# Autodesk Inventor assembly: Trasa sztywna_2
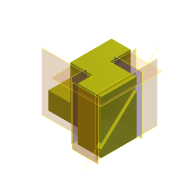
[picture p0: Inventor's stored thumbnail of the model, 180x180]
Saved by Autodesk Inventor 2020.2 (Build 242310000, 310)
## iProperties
Created: 2014-07
Part Number: Trasa sztywna_2
Document SubType Name: Assembly
Designer: F.Stasiak
Catalog Web Link: www.expertbooks.pl
Manager: www.cadconsulting.pl
Company: Fabian Stasiak CAD Consulting
Author: F.Stasiak
Subject: Zbiór ćwiczeń. Autodesk Inventor 2020. Kurs Professional
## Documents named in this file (2)
- C:\2020_Kurs_Professional\R1 Rury\Trasa sztywna_2.iam
- C:\2020_Kurs_Professional\R1 Rury\Konstrukcja_2.ipt
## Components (1 placed, 1 different names)
1. Konstrukcja_2:1
